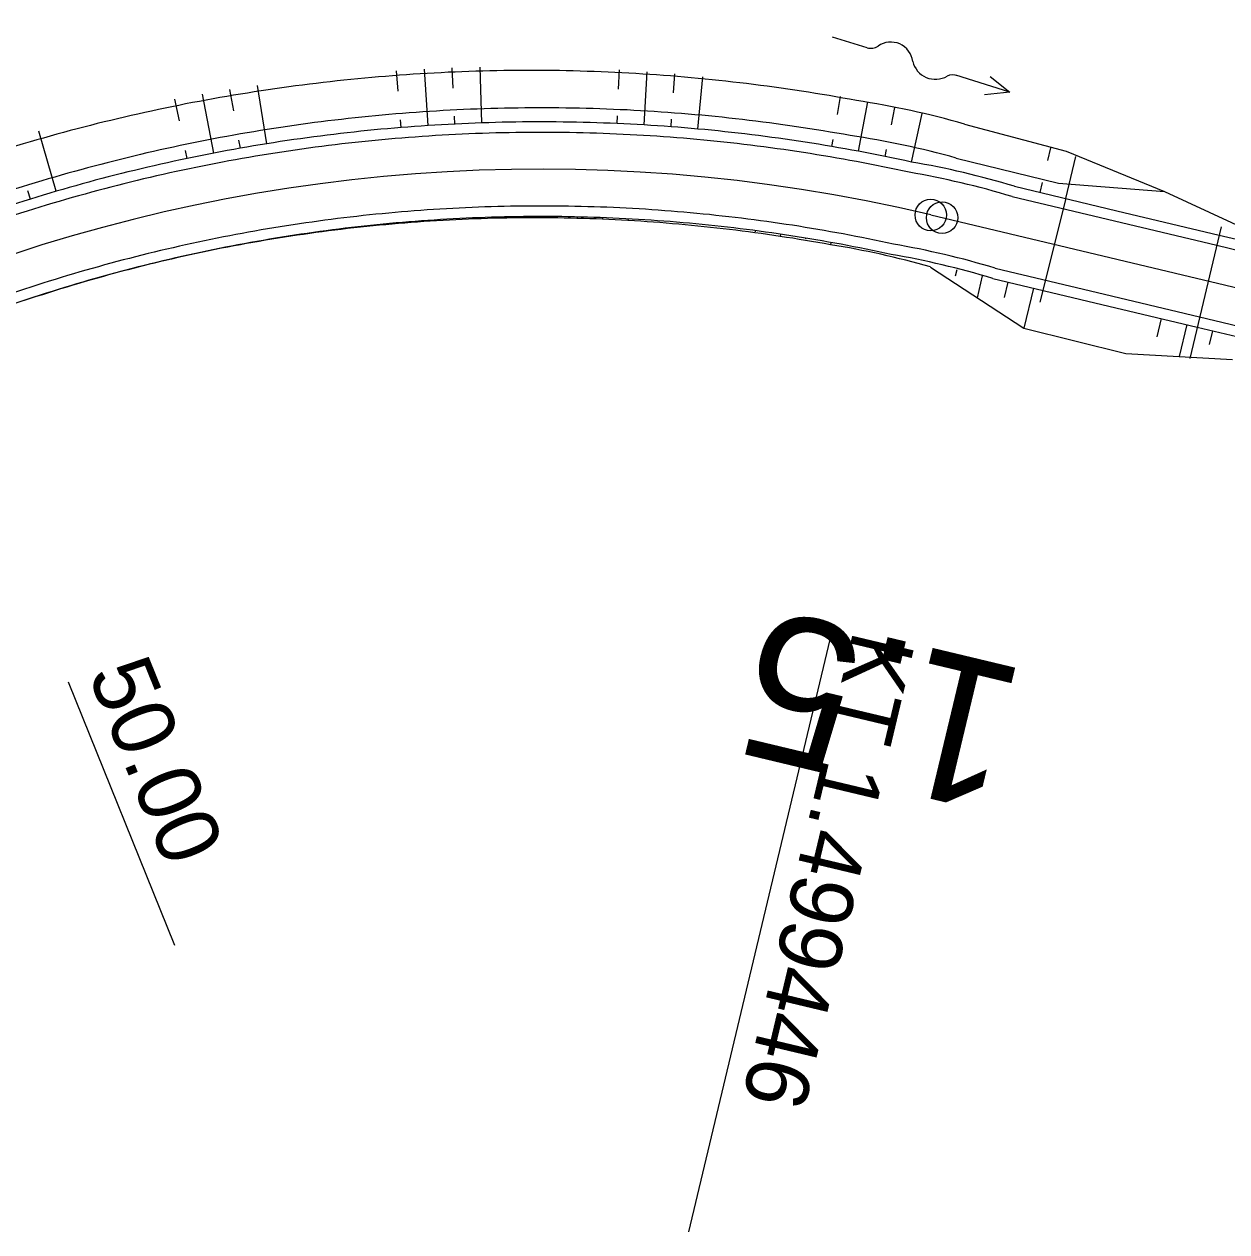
# Model space of a CAD drawing. Extents: x -481656 to -478728, y -1113199 to -1110710.
# Drawn here: x -478920.3 to -478863.1, y -1110767.8 to -1110710.3 of the extents above; entities that cross this region are included whole.
import ezdxf

# ---------------------------------------------------------------- set-up
doc = ezdxf.new("R2010")
doc.units = 0
for name, color, linetype in [('C5_HATCH_SLOPE_L', 7, 'Continuous'), ('C5_HATCH_SLOPE_R', 7, 'Continuous'), ('C5_HECTOMETRY', 7, 'Continuous'), ('C5_HLBODY', 7, 'Continuous'), ('C5_HRANA_TELESO', 7, 'Continuous'), ('C5_KORUNA', 7, 'Continuous'), ('C5_OSA', 7, 'Continuous'), ('C5_PRIKOP', 7, 'Continuous'), ('C5_STANICENI', 7, 'Continuous'), ('C5_ZPEVKRAJ', 7, 'Continuous'), ('DRENÁŽ', 7, 'Continuous'), ('PLYN', 7, 'Continuous'), ('PROPUSTEK', 7, 'Continuous')]:
    doc.layers.add(name, color=color, linetype=linetype)

# ---------------------------------------------------------------- blocks, each defined once
blk = doc.blocks.new('A$C70B')
at = {"layer": 'DRENÁŽ'}
for p, q in [((0.869, 0.002), (-0.869, -0.002)), ((6.861, 0.426), (7.971, -0.002)), ((7.971, -0.002), (5.275, -0.002)), ((7.971, -0.002), (6.862, -0.478))]:
    blk.add_line(p, q, dxfattribs=at)
for centre, radius, start, end in [((2.168, -0.416), 1.055, 24.40393, 142.08362), ((0.872, 0.584), 0.582, 269.69241, 322.79009), ((4.08, 0.589), 1.109, 210.88731, 317.37071), ((5.319, -0.636), 0.636, 85.97658, 131.72478)]:
    blk.add_arc(centre, radius, start, end, dxfattribs=at)

msp = doc.modelspace()

# ---------------------------------------------------------------- linework, layer by layer
at = {"layer": 'C5_HATCH_SLOPE_L'}
for p, q in [((-478902.508, -1110713.534), (-478902.587, -1110712.559)), ((-478901.087, -1110715.165), (-478901.262, -1110712.48)), ((-478899.888, -1110713.385), (-478899.936, -1110712.422)), ((-478898.52, -1110715.037), (-478898.61, -1110712.385)), ((-478892.024, -1110713.43), (-478891.983, -1110712.514)), ((-478890.812, -1110715.135), (-478890.661, -1110712.602)), ((-478889.408, -1110713.61), (-478889.341, -1110712.711)), ((-478888.249, -1110715.328), (-478888.022, -1110712.84)), ((-478908.746, -1110716.028), (-478909.191, -1110713.254)), ((-478912.911, -1110714.938), (-478913.125, -1110713.914)), ((-478911.277, -1110716.475), (-478911.817, -1110713.673)), ((-478910.327, -1110714.466), (-478910.506, -1110713.453)), ((-478881.618, -1110714.632), (-478881.474, -1110713.787)), ((-478880.614, -1110716.387), (-478880.175, -1110714.037)), ((-478879.048, -1110715.134), (-478878.88, -1110714.307)), ((-478902.368, -1110715.259), (-478902.398, -1110714.884)), ((-478899.804, -1110715.091), (-478899.822, -1110714.72)), ((-478892.095, -1110715.069), (-478892.08, -1110714.708)), ((-478889.53, -1110715.222), (-478889.503, -1110714.866)), ((-478878.095, -1110716.898), (-478877.59, -1110714.596)), ((-478918.769, -1110718.287), (-478919.604, -1110715.428)), ((-478910.013, -1110716.242), (-478910.08, -1110715.861)), ((-478881.879, -1110716.161), (-478881.821, -1110715.82)), ((-478879.353, -1110716.633), (-478879.284, -1110716.297)), ((-478871.61, -1110716.818), (-478871.468, -1110716.224)), ((-478912.537, -1110716.728), (-478912.617, -1110716.346)), ((-478870.757, -1110718.632), (-478870.28, -1110716.629)), ((-478871.973, -1110718.343), (-478871.862, -1110717.877)), ((-478920, -1110718.657), (-478920.118, -1110718.273))]:
    msp.add_line(p, q, dxfattribs=at)
at = {"layer": 'C5_HATCH_SLOPE_R'}
for p, q in [((-478901.285, -1110719.689), (-478901.282, -1110719.73)), ((-478895.216, -1110719.491), (-478895.216, -1110719.522)), ((-478895.216, -1110719.554), (-478895.216, -1110719.554)), ((-478894.001, -1110719.508), (-478894.003, -1110719.576)), ((-478892.789, -1110719.617), (-478892.789, -1110719.617)), ((-478892.787, -1110719.544), (-478892.788, -1110719.58)), ((-478891.573, -1110719.599), (-478891.577, -1110719.678)), ((-478904.913, -1110720.035), (-478904.911, -1110720.05)), ((-478904.909, -1110720.065), (-478904.909, -1110720.065)), ((-478903.705, -1110719.901), (-478903.702, -1110719.935)), ((-478902.496, -1110719.786), (-478902.494, -1110719.804)), ((-478902.493, -1110719.823), (-478902.493, -1110719.823)), ((-478885.54, -1110720.261), (-478885.54, -1110720.261)), ((-478885.526, -1110720.159), (-478885.533, -1110720.21)), ((-478884.323, -1110720.328), (-478884.339, -1110720.433)), ((-478883.141, -1110720.623), (-478883.141, -1110720.623)), ((-478883.123, -1110720.515), (-478883.132, -1110720.569)), ((-478881.926, -1110720.721), (-478881.946, -1110720.832)), ((-478912.1, -1110721.236), (-478912.099, -1110721.24)), ((-478912.098, -1110721.245), (-478912.098, -1110721.245)), ((-478910.91, -1110720.989), (-478910.908, -1110721)), ((-478914.466, -1110721.785), (-478914.465, -1110721.789)), ((-478914.464, -1110721.793), (-478914.464, -1110721.793)), ((-478913.285, -1110721.501), (-478913.283, -1110721.51)), ((-478875.942, -1110722.023), (-478876.013, -1110722.32)), ((-478876.084, -1110722.618), (-478876.084, -1110722.618)), ((-478874.726, -1110722.313), (-478874.972, -1110723.347)), ((-478873.51, -1110722.603), (-478873.686, -1110723.34)), ((-478872.294, -1110722.892), (-478872.749, -1110724.804)), ((-478873.861, -1110724.076), (-478873.861, -1110724.076)), ((-478866.214, -1110724.34), (-478866.42, -1110725.208)), ((-478864.998, -1110724.63), (-478865.359, -1110726.145)), ((-478863.782, -1110724.92), (-478863.936, -1110725.568)), ((-478866.627, -1110726.075), (-478866.627, -1110726.075)), ((-478864.091, -1110726.216), (-478864.091, -1110726.216))]:
    msp.add_line(p, q, dxfattribs=at)
at = {"layer": 'C5_HECTOMETRY'}
msp.add_circle((-478876.636, -1110719.545), 0.75, dxfattribs=at)
at = {"layer": 'C5_HLBODY'}
msp.add_line((-478881.81, -1110738.872), (-478888.692, -1110767.764), dxfattribs=at)
msp.add_circle((-478877.175, -1110719.416), 0.75, dxfattribs=at)
at = {"layer": 'C5_HRANA_TELESO'}
for p, q in [((-478875.576, -1110715.092), (-478870.744, -1110716.387)), ((-478870.744, -1110716.387), (-478866.058, -1110718.292)), ((-478866.058, -1110718.292), (-478861.433, -1110720.451)), ((-478877.195, -1110721.889), (-478872.749, -1110724.804)), ((-478872.749, -1110724.804), (-478867.895, -1110726.004)), ((-478867.895, -1110726.004), (-478862.823, -1110726.287))]:
    msp.add_line(p, q, dxfattribs=at)
for centre, radius, start, end in [((-478896.219, -1110797.29), 84.746, 93.76633, 97.34738), ((-478896.166, -1110797.256), 84.716, 90.22237, 93.80341), ((-478896.288, -1110797.224), 84.683, 86.55883, 90.1399), ((-478896.21, -1110797.195), 84.65, 83.02914, 86.61019), ((-478896.312, -1110797.337), 84.781, 97.28074, 100.86181), ((-478896.127, -1110797.177), 84.621, 79.50249, 83.08352), ((-478887.145, -1110755.783), 42.304, 74.12845, 81.24979), ((-478896.297, -1110797.372), 84.818, 100.86727, 104.44835), ((-478896.208, -1110797.386), 84.853, 104.50403, 108.08509), ((-478895.95, -1110797.263), 77.716, 93.93399, 97.51499), ((-478895.977, -1110797.249), 77.7, 90.33435, 93.91536), ((-478896.042, -1110797.231), 77.682, 86.70531, 90.28633), ((-478896.044, -1110797.21), 77.661, 83.12191, 86.70293), ((-478895.957, -1110797.279), 77.731, 97.50821, 101.08922), ((-478895.928, -1110797.207), 77.644, 79.62581, 83.20681), ((-478887.984, -1110759.178), 38.819, 73.86294, 81.05131), ((-478895.765, -1110797.251), 77.741, 101.23216, 104.81314), ((-478895.674, -1110797.227), 77.741, 104.88297, 108.46395)]:
    msp.add_arc(centre, radius, start, end, dxfattribs=at)
at = {"layer": 'C5_KORUNA'}
for p, q in [((-478873.189, -1110718.053), (-478868.325, -1110719.212)), ((-478868.325, -1110719.212), (-478863.461, -1110720.37)), ((-478863.461, -1110720.37), (-478858.597, -1110721.529)), ((-478874.232, -1110722.431), (-478869.368, -1110723.589)), ((-478869.368, -1110723.589), (-478864.504, -1110724.748)), ((-478864.504, -1110724.748), (-478859.64, -1110725.906))]:
    msp.add_line(p, q, dxfattribs=at)
for centre, radius, start, end in [((-478895.713, -1110797.239), 82.25, 91.95547, 95.53645), ((-478895.713, -1110797.239), 82.25, 88.37448, 91.95547), ((-478895.713, -1110797.239), 82.25, 84.79349, 88.37448), ((-478895.713, -1110797.239), 82.25, 95.53645, 99.11744), ((-478895.713, -1110797.239), 82.25, 81.21251, 84.79349), ((-478895.713, -1110797.239), 82.25, 99.11744, 102.69843), ((-478895.713, -1110797.239), 82.25, 77.63152, 81.21251), ((-478895.713, -1110797.239), 82.25, 102.69842, 106.27941), ((-478885.048, -1110757.431), 41.125, 73.23929, 80.26601), ((-478895.713, -1110797.239), 82.25, 106.27941, 109.86039), ((-478895.713, -1110797.239), 77.75, 91.95546, 95.53645), ((-478895.713, -1110797.239), 77.75, 88.37448, 91.95546), ((-478895.713, -1110797.239), 77.75, 84.79349, 88.37448), ((-478895.713, -1110797.239), 77.75, 95.53645, 99.11743), ((-478895.713, -1110797.239), 77.75, 81.2125, 84.79349), ((-478895.713, -1110797.239), 77.75, 99.11743, 102.69842), ((-478895.713, -1110797.239), 77.75, 77.63152, 81.2125), ((-478895.713, -1110797.239), 77.75, 102.69842, 106.27941), ((-478885.54, -1110759.625), 38.875, 73.08945, 80.40397), ((-478895.713, -1110797.239), 77.75, 106.27941, 109.86039)]:
    msp.add_arc(centre, radius, start, end, dxfattribs=at)
at = {"layer": 'C5_OSA'}
msp.add_line((-478877.175, -1110719.416), (-478731.78, -1110754.05), dxfattribs=at)
msp.add_arc((-478895.713, -1110797.239), 80, 76.60169, 146.54497, dxfattribs=at)
at = {"layer": 'C5_PRIKOP'}
for p, q in [((-478875.961, -1110716.708), (-478871.104, -1110717.898)), ((-478871.104, -1110717.898), (-478866.058, -1110718.292))]:
    msp.add_line(p, q, dxfattribs=at)
for centre, radius, start, end in [((-478895.713, -1110797.239), 82.916, 94.10982, 97.69081), ((-478895.713, -1110797.239), 82.916, 90.52884, 94.10982), ((-478895.713, -1110797.239), 82.916, 86.94785, 90.52884), ((-478895.713, -1110797.239), 82.916, 83.36686, 86.94785), ((-478895.713, -1110797.239), 82.916, 97.69081, 101.27179), ((-478895.713, -1110797.239), 82.916, 79.78588, 83.36686), ((-478887.072, -1110756.649), 41.458, 74.45404, 81.59164), ((-478895.713, -1110797.239), 82.916, 101.27179, 104.85278), ((-478895.713, -1110797.239), 82.916, 104.85278, 108.43376)]:
    msp.add_arc(centre, radius, start, end, dxfattribs=at)
at = {"layer": 'C5_STANICENI'}
msp.add_line((-478918.204, -1110741.614), (-478913.143, -1110754.13), dxfattribs=at)
at = {"layer": 'C5_ZPEVKRAJ'}
for p, q in [((-478873.305, -1110718.539), (-478868.441, -1110719.698)), ((-478868.441, -1110719.698), (-478863.577, -1110720.857)), ((-478863.577, -1110720.857), (-478858.713, -1110722.015)), ((-478874.116, -1110721.944), (-478869.252, -1110723.103)), ((-478869.252, -1110723.103), (-478864.388, -1110724.261)), ((-478864.388, -1110724.261), (-478859.524, -1110725.42))]:
    msp.add_line(p, q, dxfattribs=at)
for centre, radius, start, end in [((-478895.713, -1110797.239), 81.75, 91.95547, 95.53645), ((-478895.713, -1110797.239), 81.75, 88.37448, 91.95547), ((-478895.713, -1110797.239), 81.75, 84.79349, 88.37448), ((-478895.713, -1110797.239), 81.75, 95.53645, 99.11744), ((-478895.713, -1110797.239), 81.75, 81.21251, 84.79349), ((-478895.713, -1110797.239), 81.75, 99.11744, 102.69842), ((-478895.713, -1110797.239), 81.75, 77.63152, 81.21251), ((-478885.103, -1110757.675), 40.875, 73.22343, 80.28056), ((-478895.713, -1110797.239), 81.75, 102.69842, 106.27941), ((-478895.713, -1110797.239), 81.75, 106.27941, 109.86039), ((-478895.713, -1110797.239), 78.25, 91.95546, 95.53645), ((-478895.713, -1110797.239), 78.25, 88.37448, 91.95546), ((-478895.713, -1110797.239), 78.25, 84.79349, 88.37448), ((-478895.713, -1110797.239), 78.25, 95.53645, 99.11743), ((-478895.713, -1110797.239), 78.25, 81.21251, 84.79349), ((-478895.713, -1110797.239), 78.25, 99.11743, 102.69842), ((-478895.713, -1110797.239), 78.25, 77.63152, 81.21251), ((-478895.713, -1110797.239), 78.25, 102.69842, 106.27941), ((-478885.485, -1110759.381), 39.125, 73.10693, 80.38783), ((-478895.713, -1110797.239), 78.25, 106.27941, 109.86039)]:
    msp.add_arc(centre, radius, start, end, dxfattribs=at)
at = {"layer": 'PROPUSTEK'}
for p, q in [((-478870.757, -1110718.632), (-478871.995, -1110723.566)), ((-478863.367, -1110719.975), (-478864.859, -1110726.237))]:
    msp.add_line(p, q, dxfattribs=at)

# ---------------------------------------------------------------- block references
at = {"layer": 'PLYN', "rotation": -17.220780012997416}
msp.add_blockref('A$C70B', (-478881.027, -1110711.21), dxfattribs=at)

# ---------------------------------------------------------------- texts
at = {"layer": 'C5_HECTOMETRY'}
msp.add_text('1.5', height=6.999, rotation=166.55607, dxfattribs=at).set_placement((-478872.47, -1110741.104))
at = {"layer": 'C5_HLBODY'}
msp.add_text('KT 1.499446', height=2.999, rotation=256.60169, dxfattribs=at).set_placement((-478880.837, -1110739.103))
at = {"layer": 'C5_STANICENI'}
msp.add_text('50.00', height=3, rotation=292.01475, dxfattribs=at).set_placement((-478917.277, -1110741.238))

doc.saveas('drawing.dxf')
